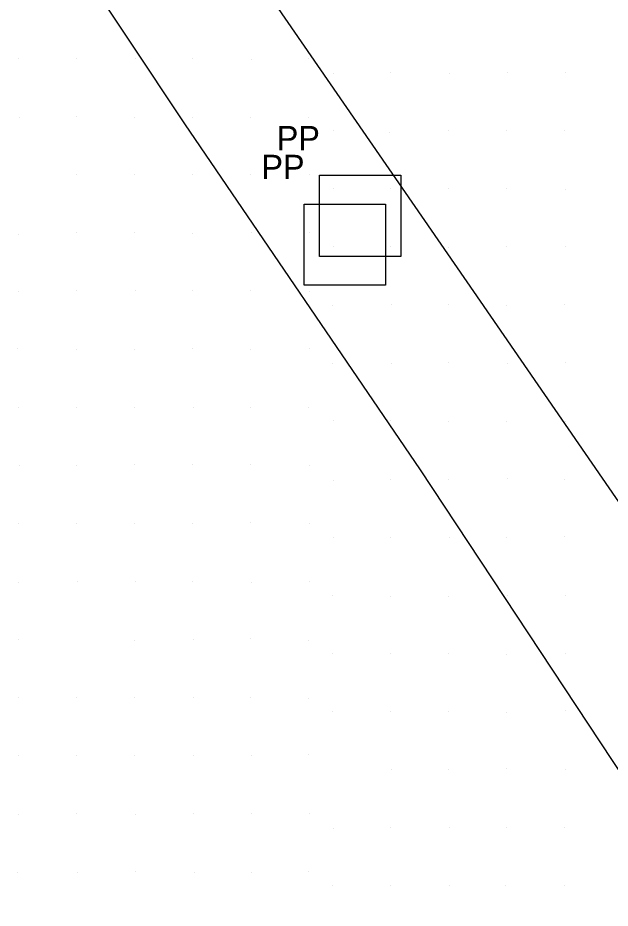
# Model space of a CAD drawing. Extents: x 1602514 to 1609837, y 863887 to 871157.
# Drawn here: x 1604012.4 to 1604165.5, y 868686.5 to 868916.6 of the extents above; entities that cross this region are included whole.
import ezdxf

# ---------------------------------------------------------------- set-up
doc = ezdxf.new("R2010")
doc.units = 0
for name, color, linetype in [('Survey-Spot dirt', 7, 'Continuous'), ('Survey-Vegetation trees', 7, 'Continuous'), ('Utility-Pole', 7, 'Continuous')]:
    doc.layers.add(name, color=color, linetype=linetype)

msp = doc.modelspace()

# ---------------------------------------------------------------- linework, layer by layer
at = {"layer": 'Survey-Spot dirt'}
for p, q in [((1604012.67, 868906), (1604012.67, 868906)), ((1604012.67, 868906), (1604012.67, 868906)), ((1604027.68, 868906), (1604027.68, 868906)), ((1604027.68, 868906), (1604027.68, 868906)), ((1604042.73, 868906), (1604042.73, 868906)), ((1604042.73, 868906), (1604042.73, 868906)), ((1604057.6, 868906.05), (1604057.6, 868906.05)), ((1604057.6, 868906.05), (1604057.6, 868906.05)), ((1604072.66, 868905.95), (1604072.66, 868905.95)), ((1604072.66, 868905.95), (1604072.66, 868905.95)), ((1604087.51, 868906.18), (1604087.51, 868906.18)), ((1604087.51, 868906.18), (1604087.51, 868906.18)), ((1604093.89, 868902.37), (1604093.89, 868902.37)), ((1604093.89, 868902.37), (1604093.89, 868902.37)), ((1604108.78, 868902.39), (1604108.78, 868902.39)), ((1604108.78, 868902.39), (1604108.78, 868902.39)), ((1604123.85, 868902.3), (1604123.85, 868902.3)), ((1604123.85, 868902.3), (1604123.85, 868902.3)), ((1604138.92, 868902.42), (1604138.92, 868902.42)), ((1604138.92, 868902.42), (1604138.92, 868902.42)), ((1604153.85, 868902.45), (1604153.85, 868902.45)), ((1604153.85, 868902.45), (1604153.85, 868902.45)), ((1604012.73, 868891), (1604012.73, 868891)), ((1604012.73, 868891), (1604012.73, 868891)), ((1604027.65, 868891.04), (1604027.65, 868891.04)), ((1604027.65, 868891.04), (1604027.65, 868891.04)), ((1604042.59, 868890.94), (1604042.59, 868890.94)), ((1604042.59, 868890.94), (1604042.59, 868890.94)), ((1604057.63, 868890.94), (1604057.63, 868890.94)), ((1604057.63, 868890.94), (1604057.63, 868890.94)), ((1604072.58, 868890.97), (1604072.58, 868890.97)), ((1604072.58, 868890.97), (1604072.58, 868890.97)), ((1604087.63, 868890.95), (1604087.63, 868890.95)), ((1604087.63, 868890.95), (1604087.63, 868890.95)), ((1604093.98, 868887.45), (1604093.98, 868887.45)), ((1604093.98, 868887.45), (1604093.98, 868887.45)), ((1604123.74, 868887.42), (1604123.74, 868887.42)), ((1604123.74, 868887.42), (1604123.74, 868887.42)), ((1604138.79, 868887.47), (1604138.79, 868887.47)), ((1604138.79, 868887.47), (1604138.79, 868887.47)), ((1604108.47, 868887.08), (1604108.47, 868887.08)), ((1604108.47, 868887.08), (1604108.47, 868887.08)), ((1604153.78, 868887.39), (1604153.78, 868887.39)), ((1604153.78, 868887.39), (1604153.78, 868887.39)), ((1604027.62, 868876.15), (1604027.62, 868876.15)), ((1604027.62, 868876.15), (1604027.62, 868876.15)), ((1604042.59, 868876.04), (1604042.59, 868876.04)), ((1604042.59, 868876.04), (1604042.59, 868876.04)), ((1604057.49, 868876.05), (1604057.49, 868876.05)), ((1604057.49, 868876.05), (1604057.49, 868876.05)), ((1604072.61, 868876.04), (1604072.61, 868876.04)), ((1604072.61, 868876.04), (1604072.61, 868876.04)), ((1604087.74, 868876.11), (1604087.74, 868876.11)), ((1604087.74, 868876.11), (1604087.74, 868876.11)), ((1604093.86, 868872.45), (1604093.86, 868872.45)), ((1604093.86, 868872.45), (1604093.86, 868872.45)), ((1604108.66, 868872.45), (1604108.66, 868872.45)), ((1604108.66, 868872.45), (1604108.66, 868872.45)), ((1604123.76, 868872.42), (1604123.76, 868872.42)), ((1604123.76, 868872.42), (1604123.76, 868872.42)), ((1604138.77, 868872.54), (1604138.77, 868872.54)), ((1604138.77, 868872.54), (1604138.77, 868872.54)), ((1604153.88, 868872.3), (1604153.88, 868872.3)), ((1604153.88, 868872.3), (1604153.88, 868872.3)), ((1604012.69, 868860.68), (1604012.69, 868860.68)), ((1604012.69, 868860.68), (1604012.69, 868860.68)), ((1604027.57, 868861.11), (1604027.57, 868861.11)), ((1604027.57, 868861.11), (1604027.57, 868861.11)), ((1604042.54, 868861.06), (1604042.54, 868861.06)), ((1604042.54, 868861.06), (1604042.54, 868861.06)), ((1604057.65, 868860.97), (1604057.65, 868860.97)), ((1604057.65, 868860.97), (1604057.65, 868860.97)), ((1604072.71, 868861.1), (1604072.71, 868861.1)), ((1604072.71, 868861.1), (1604072.71, 868861.1)), ((1604087.74, 868861.09), (1604087.74, 868861.09)), ((1604087.74, 868861.09), (1604087.74, 868861.09)), ((1604138.72, 868857.59), (1604138.72, 868857.59)), ((1604138.72, 868857.59), (1604138.72, 868857.59)), ((1604093.9, 868857.42), (1604093.9, 868857.42)), ((1604093.9, 868857.42), (1604093.9, 868857.42)), ((1604108.67, 868857.42), (1604108.67, 868857.42)), ((1604108.67, 868857.42), (1604108.67, 868857.42)), ((1604123.71, 868857.34), (1604123.71, 868857.34)), ((1604123.71, 868857.34), (1604123.71, 868857.34)), ((1604153.79, 868857.42), (1604153.79, 868857.42)), ((1604153.79, 868857.42), (1604153.79, 868857.42)), ((1604012.63, 868846), (1604012.63, 868846)), ((1604012.63, 868846), (1604012.63, 868846)), ((1604027.57, 868846.04), (1604027.57, 868846.04)), ((1604027.57, 868846.04), (1604027.57, 868846.04)), ((1604042.78, 868846.04), (1604042.78, 868846.04)), ((1604042.78, 868846.04), (1604042.78, 868846.04)), ((1604057.66, 868846.12), (1604057.66, 868846.12)), ((1604057.66, 868846.12), (1604057.66, 868846.12)), ((1604072.52, 868846.1), (1604072.52, 868846.1)), ((1604072.52, 868846.1), (1604072.52, 868846.1)), ((1604087.67, 868846), (1604087.67, 868846)), ((1604087.67, 868846), (1604087.67, 868846)), ((1604093.82, 868842.29), (1604093.82, 868842.29)), ((1604093.82, 868842.29), (1604093.82, 868842.29)), ((1604108.84, 868842.44), (1604108.84, 868842.44)), ((1604108.84, 868842.44), (1604108.84, 868842.44)), ((1604123.76, 868842.47), (1604123.76, 868842.47)), ((1604123.76, 868842.47), (1604123.76, 868842.47)), ((1604138.59, 868842.33), (1604138.59, 868842.33)), ((1604138.59, 868842.33), (1604138.59, 868842.33)), ((1604153.74, 868842.53), (1604153.74, 868842.53)), ((1604153.74, 868842.53), (1604153.74, 868842.53)), ((1604012.41, 868831.05), (1604012.41, 868831.05)), ((1604012.41, 868831.05), (1604012.41, 868831.05)), ((1604027.68, 868830.97), (1604027.68, 868830.97)), ((1604027.68, 868830.97), (1604027.68, 868830.97)), ((1604042.62, 868831.01), (1604042.62, 868831.01)), ((1604042.62, 868831.01), (1604042.62, 868831.01)), ((1604057.62, 868831.07), (1604057.62, 868831.07)), ((1604057.62, 868831.07), (1604057.62, 868831.07)), ((1604072.51, 868830.97), (1604072.51, 868830.97)), ((1604072.51, 868830.97), (1604072.51, 868830.97)), ((1604087.67, 868831.05), (1604087.67, 868831.05)), ((1604087.67, 868831.05), (1604087.67, 868831.05)), ((1604123.7, 868827.57), (1604123.7, 868827.57)), ((1604123.7, 868827.57), (1604123.7, 868827.57)), ((1604093.82, 868827.42), (1604093.82, 868827.42)), ((1604093.82, 868827.42), (1604093.82, 868827.42)), ((1604108.85, 868827.33), (1604108.85, 868827.33)), ((1604108.85, 868827.33), (1604108.85, 868827.33)), ((1604138.82, 868827.26), (1604138.82, 868827.26)), ((1604138.82, 868827.26), (1604138.82, 868827.26)), ((1604153.88, 868827.51), (1604153.88, 868827.51)), ((1604153.88, 868827.51), (1604153.88, 868827.51)), ((1604012.62, 868816), (1604012.62, 868816)), ((1604012.62, 868816), (1604012.62, 868816)), ((1604027.54, 868815.91), (1604027.54, 868815.91)), ((1604027.54, 868815.91), (1604027.54, 868815.91)), ((1604042.64, 868815.95), (1604042.64, 868815.95)), ((1604042.64, 868815.95), (1604042.64, 868815.95)), ((1604057.71, 868815.95), (1604057.71, 868815.95)), ((1604057.71, 868815.95), (1604057.71, 868815.95)), ((1604072.61, 868815.98), (1604072.61, 868815.98)), ((1604072.61, 868815.98), (1604072.61, 868815.98)), ((1604087.63, 868816.02), (1604087.63, 868816.02)), ((1604087.63, 868816.02), (1604087.63, 868816.02)), ((1604093.87, 868812.47), (1604093.87, 868812.47)), ((1604093.87, 868812.47), (1604093.87, 868812.47)), ((1604108.7, 868812.45), (1604108.7, 868812.45)), ((1604108.7, 868812.45), (1604108.7, 868812.45)), ((1604123.76, 868812.4), (1604123.76, 868812.4)), ((1604123.76, 868812.4), (1604123.76, 868812.4)), ((1604138.79, 868812.29), (1604138.79, 868812.29)), ((1604138.79, 868812.29), (1604138.79, 868812.29)), ((1604153.82, 868812.41), (1604153.82, 868812.41)), ((1604153.82, 868812.41), (1604153.82, 868812.41)), ((1604012.78, 868800.88), (1604012.78, 868800.88)), ((1604012.78, 868800.88), (1604012.78, 868800.88)), ((1604027.5, 868800.92), (1604027.5, 868800.92)), ((1604027.5, 868800.92), (1604027.5, 868800.92)), ((1604042.51, 868801.13), (1604042.51, 868801.13)), ((1604042.51, 868801.13), (1604042.51, 868801.13)), ((1604057.6, 868801.06), (1604057.6, 868801.06)), ((1604057.6, 868801.06), (1604057.6, 868801.06)), ((1604072.52, 868801.15), (1604072.52, 868801.15)), ((1604072.52, 868801.15), (1604072.52, 868801.15)), ((1604087.66, 868800.95), (1604087.66, 868800.95)), ((1604087.66, 868800.95), (1604087.66, 868800.95)), ((1604093.89, 868797.16), (1604093.89, 868797.16)), ((1604093.89, 868797.16), (1604093.89, 868797.16)), ((1604108.8, 868797.36), (1604108.8, 868797.36)), ((1604108.8, 868797.36), (1604108.8, 868797.36)), ((1604123.68, 868797.41), (1604123.68, 868797.41)), ((1604123.68, 868797.41), (1604123.68, 868797.41)), ((1604138.81, 868797.5), (1604138.81, 868797.5)), ((1604138.81, 868797.5), (1604138.81, 868797.5)), ((1604153.7, 868797.34), (1604153.7, 868797.34)), ((1604153.7, 868797.34), (1604153.7, 868797.34)), ((1604012.63, 868785.94), (1604012.63, 868785.94)), ((1604012.63, 868785.94), (1604012.63, 868785.94)), ((1604027.62, 868785.93), (1604027.62, 868785.93)), ((1604027.62, 868785.93), (1604027.62, 868785.93)), ((1604042.66, 868786.03), (1604042.66, 868786.03)), ((1604042.66, 868786.03), (1604042.66, 868786.03)), ((1604057.56, 868785.98), (1604057.56, 868785.98)), ((1604057.56, 868785.98), (1604057.56, 868785.98)), ((1604072.59, 868786.08), (1604072.59, 868786.08)), ((1604072.59, 868786.08), (1604072.59, 868786.08)), ((1604087.66, 868785.99), (1604087.66, 868785.99)), ((1604087.66, 868785.99), (1604087.66, 868785.99)), ((1604093.95, 868782.32), (1604093.95, 868782.32)), ((1604093.95, 868782.32), (1604093.95, 868782.32)), ((1604108.79, 868782.28), (1604108.79, 868782.28)), ((1604108.79, 868782.28), (1604108.79, 868782.28)), ((1604123.9, 868782.34), (1604123.9, 868782.34)), ((1604123.9, 868782.34), (1604123.9, 868782.34)), ((1604138.65, 868782.32), (1604138.65, 868782.32)), ((1604138.65, 868782.32), (1604138.65, 868782.32)), ((1604153.76, 868782.52), (1604153.76, 868782.52)), ((1604153.76, 868782.52), (1604153.76, 868782.52)), ((1604012.7, 868770.8), (1604012.7, 868770.8)), ((1604012.7, 868770.8), (1604012.7, 868770.8)), ((1604027.76, 868770.91), (1604027.76, 868770.91)), ((1604027.76, 868770.91), (1604027.76, 868770.91)), ((1604042.79, 868770.91), (1604042.79, 868770.91)), ((1604042.79, 868770.91), (1604042.79, 868770.91)), ((1604057.61, 868770.93), (1604057.61, 868770.93)), ((1604057.61, 868770.93), (1604057.61, 868770.93)), ((1604072.73, 868770.7), (1604072.73, 868770.7)), ((1604072.73, 868770.7), (1604072.73, 868770.7)), ((1604087.69, 868770.92), (1604087.69, 868770.92)), ((1604087.69, 868770.92), (1604087.69, 868770.92)), ((1604093.83, 868767.22), (1604093.83, 868767.22)), ((1604093.83, 868767.22), (1604093.83, 868767.22)), ((1604108.68, 868767.14), (1604108.68, 868767.14)), ((1604108.68, 868767.14), (1604108.68, 868767.14)), ((1604123.75, 868767.14), (1604123.75, 868767.14)), ((1604123.75, 868767.14), (1604123.75, 868767.14)), ((1604139.03, 868767.35), (1604139.03, 868767.35)), ((1604139.03, 868767.35), (1604139.03, 868767.35)), ((1604153.84, 868767.3), (1604153.84, 868767.3)), ((1604153.84, 868767.3), (1604153.84, 868767.3)), ((1604072.42, 868756.28), (1604072.42, 868756.28)), ((1604072.42, 868756.28), (1604072.42, 868756.28)), ((1604012.7, 868755.93), (1604012.7, 868755.93)), ((1604012.7, 868755.93), (1604012.7, 868755.93)), ((1604042.54, 868755.71), (1604042.54, 868755.71)), ((1604042.54, 868755.71), (1604042.54, 868755.71)), ((1604057.7, 868755.96), (1604057.7, 868755.96)), ((1604057.7, 868755.96), (1604057.7, 868755.96)), ((1604087.58, 868755.77), (1604087.58, 868755.77)), ((1604087.58, 868755.77), (1604087.58, 868755.77)), ((1604093.8, 868752.34), (1604093.8, 868752.34)), ((1604093.8, 868752.34), (1604093.8, 868752.34)), ((1604108.82, 868752.38), (1604108.82, 868752.38)), ((1604108.82, 868752.38), (1604108.82, 868752.38)), ((1604123.72, 868752.31), (1604123.72, 868752.31)), ((1604123.72, 868752.31), (1604123.72, 868752.31)), ((1604138.66, 868752.06), (1604138.66, 868752.06)), ((1604138.66, 868752.06), (1604138.66, 868752.06)), ((1604153.89, 868752.32), (1604153.89, 868752.32)), ((1604153.89, 868752.32), (1604153.89, 868752.32)), ((1604012.67, 868740.86), (1604012.67, 868740.86)), ((1604012.67, 868740.86), (1604012.67, 868740.86)), ((1604027.6, 868740.95), (1604027.6, 868740.95)), ((1604027.6, 868740.95), (1604027.6, 868740.95)), ((1604042.62, 868740.94), (1604042.62, 868740.94)), ((1604042.62, 868740.94), (1604042.62, 868740.94)), ((1604057.69, 868741.04), (1604057.69, 868741.04)), ((1604057.69, 868741.04), (1604057.69, 868741.04)), ((1604072.54, 868740.84), (1604072.54, 868740.84)), ((1604072.54, 868740.84), (1604072.54, 868740.84)), ((1604087.6, 868740.82), (1604087.6, 868740.82)), ((1604087.6, 868740.82), (1604087.6, 868740.82)), ((1604093.82, 868737.44), (1604093.82, 868737.44)), ((1604093.82, 868737.44), (1604093.82, 868737.44)), ((1604108.78, 868737.34), (1604108.78, 868737.34)), ((1604108.78, 868737.34), (1604108.78, 868737.34)), ((1604123.68, 868737.33), (1604123.68, 868737.33)), ((1604123.68, 868737.33), (1604123.68, 868737.33)), ((1604138.78, 868737.21), (1604138.78, 868737.21)), ((1604138.78, 868737.21), (1604138.78, 868737.21)), ((1604153.89, 868737.48), (1604153.89, 868737.48)), ((1604153.89, 868737.48), (1604153.89, 868737.48)), ((1604012.7, 868725.92), (1604012.7, 868725.92)), ((1604012.7, 868725.92), (1604012.7, 868725.92)), ((1604027.58, 868726.01), (1604027.58, 868726.01)), ((1604027.58, 868726.01), (1604027.58, 868726.01)), ((1604042.6, 868726), (1604042.6, 868726)), ((1604042.6, 868726), (1604042.6, 868726)), ((1604057.82, 868726.05), (1604057.82, 868726.05)), ((1604057.82, 868726.05), (1604057.82, 868726.05)), ((1604072.74, 868725.98), (1604072.74, 868725.98)), ((1604072.74, 868725.98), (1604072.74, 868725.98)), ((1604087.49, 868726.12), (1604087.49, 868726.12)), ((1604087.49, 868726.12), (1604087.49, 868726.12)), ((1604108.88, 868722.25), (1604108.88, 868722.25)), ((1604108.88, 868722.25), (1604108.88, 868722.25)), ((1604123.78, 868722.35), (1604123.78, 868722.35)), ((1604123.78, 868722.35), (1604123.78, 868722.35)), ((1604138.69, 868722.53), (1604138.69, 868722.53)), ((1604138.69, 868722.53), (1604138.69, 868722.53)), ((1604153.81, 868722.32), (1604153.81, 868722.32)), ((1604153.81, 868722.32), (1604153.81, 868722.32)), ((1604012.54, 868710.81), (1604012.54, 868710.81)), ((1604012.54, 868710.81), (1604012.54, 868710.81)), ((1604027.69, 868710.86), (1604027.69, 868710.86)), ((1604027.69, 868710.86), (1604027.69, 868710.86)), ((1604042.69, 868710.78), (1604042.69, 868710.78)), ((1604042.69, 868710.78), (1604042.69, 868710.78)), ((1604057.71, 868711.02), (1604057.71, 868711.02)), ((1604057.71, 868711.02), (1604057.71, 868711.02)), ((1604072.67, 868711), (1604072.67, 868711)), ((1604072.67, 868711), (1604072.67, 868711)), ((1604087.81, 868710.89), (1604087.81, 868710.89)), ((1604087.81, 868710.89), (1604087.81, 868710.89)), ((1604093.92, 868707.03), (1604093.92, 868707.03)), ((1604093.92, 868707.03), (1604093.92, 868707.03)), ((1604108.72, 868707.27), (1604108.72, 868707.27)), ((1604108.72, 868707.27), (1604108.72, 868707.27)), ((1604123.93, 868707.26), (1604123.93, 868707.26)), ((1604123.93, 868707.26), (1604123.93, 868707.26)), ((1604138.72, 868707.42), (1604138.72, 868707.42)), ((1604138.72, 868707.42), (1604138.72, 868707.42)), ((1604153.75, 868707.49), (1604153.75, 868707.49)), ((1604153.75, 868707.49), (1604153.75, 868707.49)), ((1604012.42, 868695.64), (1604012.42, 868695.64)), ((1604012.42, 868695.64), (1604012.42, 868695.64)), ((1604027.82, 868695.76), (1604027.82, 868695.76)), ((1604027.82, 868695.76), (1604027.82, 868695.76)), ((1604042.83, 868696), (1604042.83, 868696)), ((1604042.83, 868696), (1604042.83, 868696)), ((1604057.97, 868695.8), (1604057.97, 868695.8)), ((1604057.97, 868695.8), (1604057.97, 868695.8)), ((1604072.74, 868695.86), (1604072.74, 868695.86)), ((1604072.74, 868695.86), (1604072.74, 868695.86)), ((1604087.63, 868696), (1604087.63, 868696)), ((1604087.63, 868696), (1604087.63, 868696)), ((1604093.65, 868692.35), (1604093.65, 868692.35)), ((1604093.65, 868692.35), (1604093.65, 868692.35)), ((1604108.77, 868692.41), (1604108.77, 868692.41)), ((1604108.77, 868692.41), (1604108.77, 868692.41)), ((1604123.94, 868692.37), (1604123.94, 868692.37)), ((1604123.94, 868692.37), (1604123.94, 868692.37)), ((1604138.53, 868692.37), (1604138.53, 868692.37)), ((1604138.53, 868692.37), (1604138.53, 868692.37)), ((1604153.74, 868692.4), (1604153.74, 868692.4)), ((1604153.74, 868692.4), (1604153.74, 868692.4))]:
    msp.add_line(p, q, dxfattribs=at)
at = {"layer": 'Survey-Vegetation trees'}
for points in [[(1603900.48, 869192.6), (1603945.48, 869133.11), (1603992.35, 869047.02), (1604059.5, 868948.34), (1604130.14, 868845.92), (1604193.97, 868753.25), (1604256.92, 868659.64), (1604319, 868563.7), (1604393.26, 868451.54), (1604466.24, 868345.62)], [(1603900.48, 869192.6), (1603945.48, 869133.11), (1603992.35, 869047.02), (1604059.5, 868948.34), (1604130.14, 868845.92), (1604193.97, 868753.25), (1604256.92, 868659.64), (1604319, 868563.7), (1604393.26, 868451.54), (1604466.24, 868345.62)], [(1604438.4, 868315.53), (1604422.08, 868346.09), (1604392.7, 868367.78), (1604368.69, 868429.14), (1604322.29, 868477.2), (1604287.55, 868532.72), (1604260.5, 868584.75), (1604236.49, 868622.08), (1604198.25, 868675.97), (1604166.07, 868724.72), (1604116.41, 868799.85), (1604055.56, 868889.2), (1603998.43, 868975.05), (1603933.15, 869071.4), (1603878.82, 869156.32), (1603857.84, 869188.75)], [(1604438.4, 868315.53), (1604422.08, 868346.09), (1604392.7, 868367.78), (1604368.69, 868429.14), (1604322.29, 868477.2), (1604287.55, 868532.72), (1604260.5, 868584.75), (1604236.49, 868622.08), (1604198.25, 868675.97), (1604166.07, 868724.72), (1604116.41, 868799.85), (1604055.56, 868889.2), (1603998.43, 868975.05), (1603933.15, 869071.4), (1603878.82, 869156.32), (1603857.84, 869188.75)]]:
    msp.add_lwpolyline(points, dxfattribs=at)
at = {"layer": 'Utility-Pole'}
for points in [[(1604090.37, 868875.95), (1604111.38, 868875.95), (1604111.38, 868854.95), (1604090.37, 868854.95)], [(1604090.37, 868875.95), (1604111.38, 868875.95), (1604111.38, 868854.95), (1604090.37, 868854.95)], [(1604086.41, 868868.51), (1604107.41, 868868.51), (1604107.41, 868847.51), (1604086.41, 868847.51)], [(1604086.41, 868868.51), (1604107.41, 868868.51), (1604107.41, 868847.51), (1604086.41, 868847.51)]]:
    msp.add_lwpolyline(points, close=True, dxfattribs=at)

# ---------------------------------------------------------------- texts
for p in [(1604079.31, 868882.42), (1604079.31, 868882.42), (1604075.35, 868874.98), (1604075.35, 868874.98)]:
    msp.add_text('PP', height=6.251, dxfattribs=at).set_placement(p)

doc.saveas('drawing.dxf')
